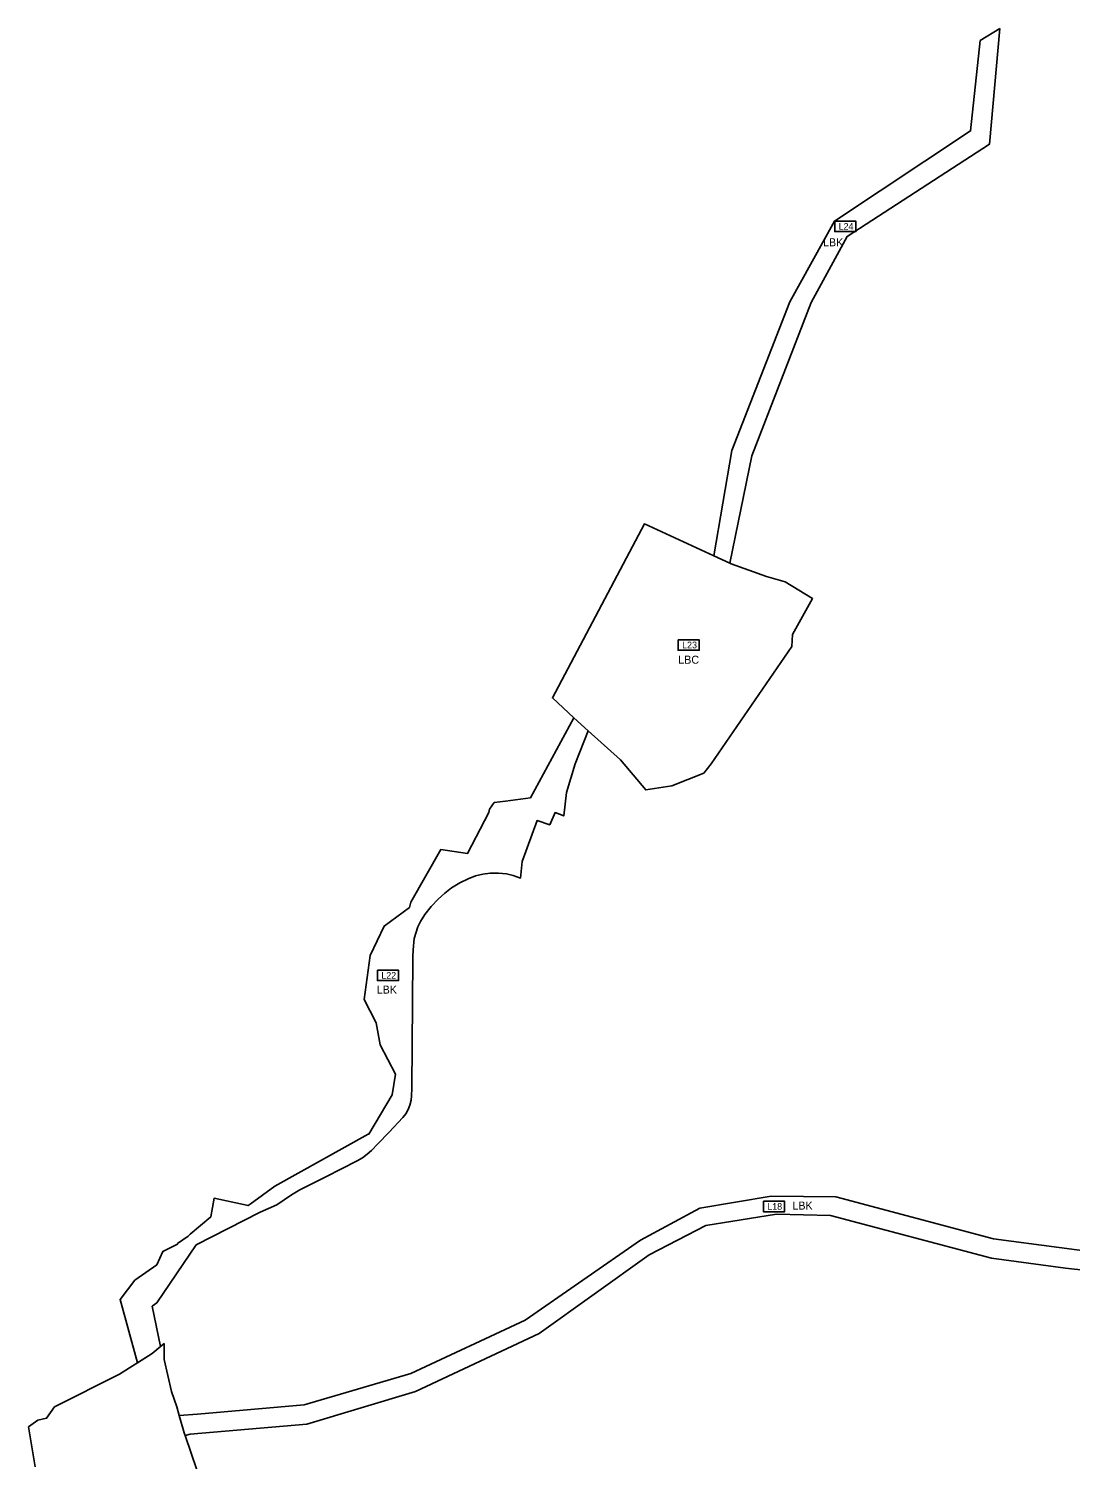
# Model space of a CAD drawing. Extents: x -546680 to -530218, y -1046521 to -1035695.
# Drawn here: x -546680 to -545119, y -1045101 to -1042956 of the extents above; entities that cross this region are included whole.
import ezdxf

# ---------------------------------------------------------------- set-up
doc = ezdxf.new("R2010")
doc.units = 0
for name, color, linetype in [('Vrstva 3', 7, 'Continuous'), ('Vrstva 32', 7, 'Continuous'), ('Vrstva 33', 7, 'Continuous'), ('Vrstva 54', 7, 'Continuous')]:
    doc.layers.add(name, color=color, linetype=linetype)

msp = doc.modelspace()

# ---------------------------------------------------------------- linework, layer by layer
at = {"layer": 'Vrstva 32'}
for points in [[(-545628.8, -1043757.2), (-545652.8, -1043746.1), (-545757, -1043698), (-545775, -1043732), (-545895, -1043959), (-545863, -1043989), (-545841.4, -1044008.4), (-545793, -1044052), (-545755, -1044097), (-545716, -1044091), (-545668, -1044072), (-545657, -1044058), (-545536, -1043882), (-545535, -1043864), (-545505, -1043810), (-545546, -1043785), (-545574, -1043777), (-545627, -1043758), (-545628.8, -1043757.2)], [(-546428, -1045116), (-546445.6, -1045064.9), (-546447, -1045061), (-546454.3, -1045035), (-546458, -1045022), (-546466, -1044999), (-546477, -1044951), (-546477, -1044927), (-546495, -1044942), (-546544, -1044973), (-546641, -1045022), (-546653, -1045039), (-546666, -1045042), (-546680, -1045051.7)], [(-546680, -1045051.7), (-546670.4, -1045111.7)]]:
    msp.add_lwpolyline(points, dxfattribs=at)
at = {"layer": 'Vrstva 33'}
for points in [[(-545224.1, -1042955.6), (-545240, -1043129), (-545453, -1043267), (-545507, -1043366), (-545596, -1043596), (-545628.8, -1043757.2), (-545652.8, -1043746.1), (-545626, -1043588), (-545539, -1043365), (-545472, -1043244), (-545268, -1043109), (-545254, -1042973.6), (-545224.1, -1042955.6)], [(-546482.3, -1044931.4), (-546495, -1044942), (-546516.8, -1044955.8), (-546543, -1044861), (-546521, -1044832), (-546488, -1044809), (-546479, -1044789), (-546457, -1044778), (-546457, -1044777), (-546441, -1044766), (-546438, -1044763), (-546407, -1044737), (-546402, -1044709), (-546351, -1044720), (-546348, -1044718), (-546311, -1044691), (-546171, -1044613), (-546170, -1044613), (-546135, -1044554), (-546130, -1044523), (-546153, -1044479), (-546159, -1044446), (-546177, -1044411), (-546168, -1044345), (-546147, -1044301), (-546109, -1044273), (-546107, -1044265), (-546062, -1044186), (-546022, -1044192), (-545990, -1044131), (-545989, -1044126), (-545982, -1044116), (-545965, -1044114), (-545928, -1044109), (-545863, -1043989), (-545841.4, -1044008.4), (-545861, -1044058), (-545874, -1044101), (-545878, -1044136), (-545891, -1044131), (-545899, -1044149), (-545918, -1044143), (-545940, -1044204), (-545942.8, -1044229.2), (-545953.5, -1044225.2), (-545963.7, -1044222.9), (-545975.7, -1044221.5), (-545988.2, -1044221.7), (-545999, -1044223.3), (-546010.3, -1044225.9), (-546021.3, -1044230.1), (-546033.7, -1044236.4), (-546046.2, -1044243.8), (-546056.1, -1044251.8), (-546066.1, -1044260.9), (-546076.5, -1044271.9), (-546086.2, -1044283.8), (-546092.7, -1044294), (-546096.8, -1044302.1), (-546102.1, -1044319.7), (-546103.8, -1044336.8), (-546104, -1044347.3), (-546104.8, -1044417.5), (-546105, -1044477.9), (-546105.5, -1044544.7), (-546105.9, -1044555.3), (-546106.8, -1044562.1), (-546108.6, -1044569.5), (-546111, -1044576.1), (-546114.4, -1044582.4), (-546119, -1044588.2), (-546139.5, -1044610.2), (-546156.6, -1044627.7), (-546166, -1044637.4), (-546172.4, -1044643.1), (-546179.4, -1044648.3), (-546187.4, -1044653.1), (-546234.7, -1044676.8), (-546273.3, -1044696.6), (-546286.1, -1044704.1), (-546308, -1044718.8), (-546333, -1044730), (-546429, -1044779), (-546488, -1044866), (-546495, -1044871), (-546482.3, -1044931.4)], [(-546445.6, -1045064.9), (-546447, -1045061), (-546454.3, -1045035), (-546427, -1045033), (-546267, -1045019), (-546107, -1044972), (-545936, -1044892), (-545763, -1044772), (-545674, -1044724), (-545567, -1044706), (-545470, -1044707), (-545234, -1044770), (-545037, -1044796)], [(-545007, -1044827), (-545126, -1044814), (-545237, -1044799), (-545478, -1044735), (-545559, -1044733), (-545665, -1044750), (-545750, -1044794), (-545915, -1044912), (-546100, -1044999), (-546263, -1045048), (-546438, -1045063), (-546445.6, -1045064.9)]]:
    msp.add_lwpolyline(points, dxfattribs=at)
at = {"layer": 'Vrstva 54'}
for points in [[(-545471.6, -1043244.3), (-545471.6, -1043259.8), (-545439.9, -1043259.8), (-545439.9, -1043244.3), (-545471.6, -1043244.3)], [(-545706.5, -1043871.9), (-545706.5, -1043887.4), (-545674.8, -1043887.4), (-545674.8, -1043871.9), (-545706.5, -1043871.9)], [(-546157.2, -1044367.2), (-546157.2, -1044382.8), (-546125.5, -1044382.8), (-546125.5, -1044367.2), (-546157.2, -1044367.2)], [(-545578.7, -1044713.6), (-545578.7, -1044729.2), (-545547, -1044729.2), (-545547, -1044713.6), (-545578.7, -1044713.6)]]:
    msp.add_lwpolyline(points, dxfattribs=at)

# ---------------------------------------------------------------- texts
at = {"layer": 'Vrstva 3'}
for s, p in [('LBK', (-545489.3, -1043281.9)), ('LBC', (-545706.3, -1043907.7)), ('LBK', (-546158.3, -1044402.3)), ('LBK', (-545535.2, -1044726.1))]:
    msp.add_text(s, height=12, dxfattribs=at).set_placement(p)
at = {"layer": 'Vrstva 54'}
for s, p in [('L24', (-545465.9, -1043257)), ('L23', (-545700.5, -1043884.6)), ('L22', (-546151.4, -1044380)), ('L18', (-545572.9, -1044726.4))]:
    msp.add_text(s, height=10, dxfattribs=at).set_placement(p)

doc.saveas('drawing.dxf')
